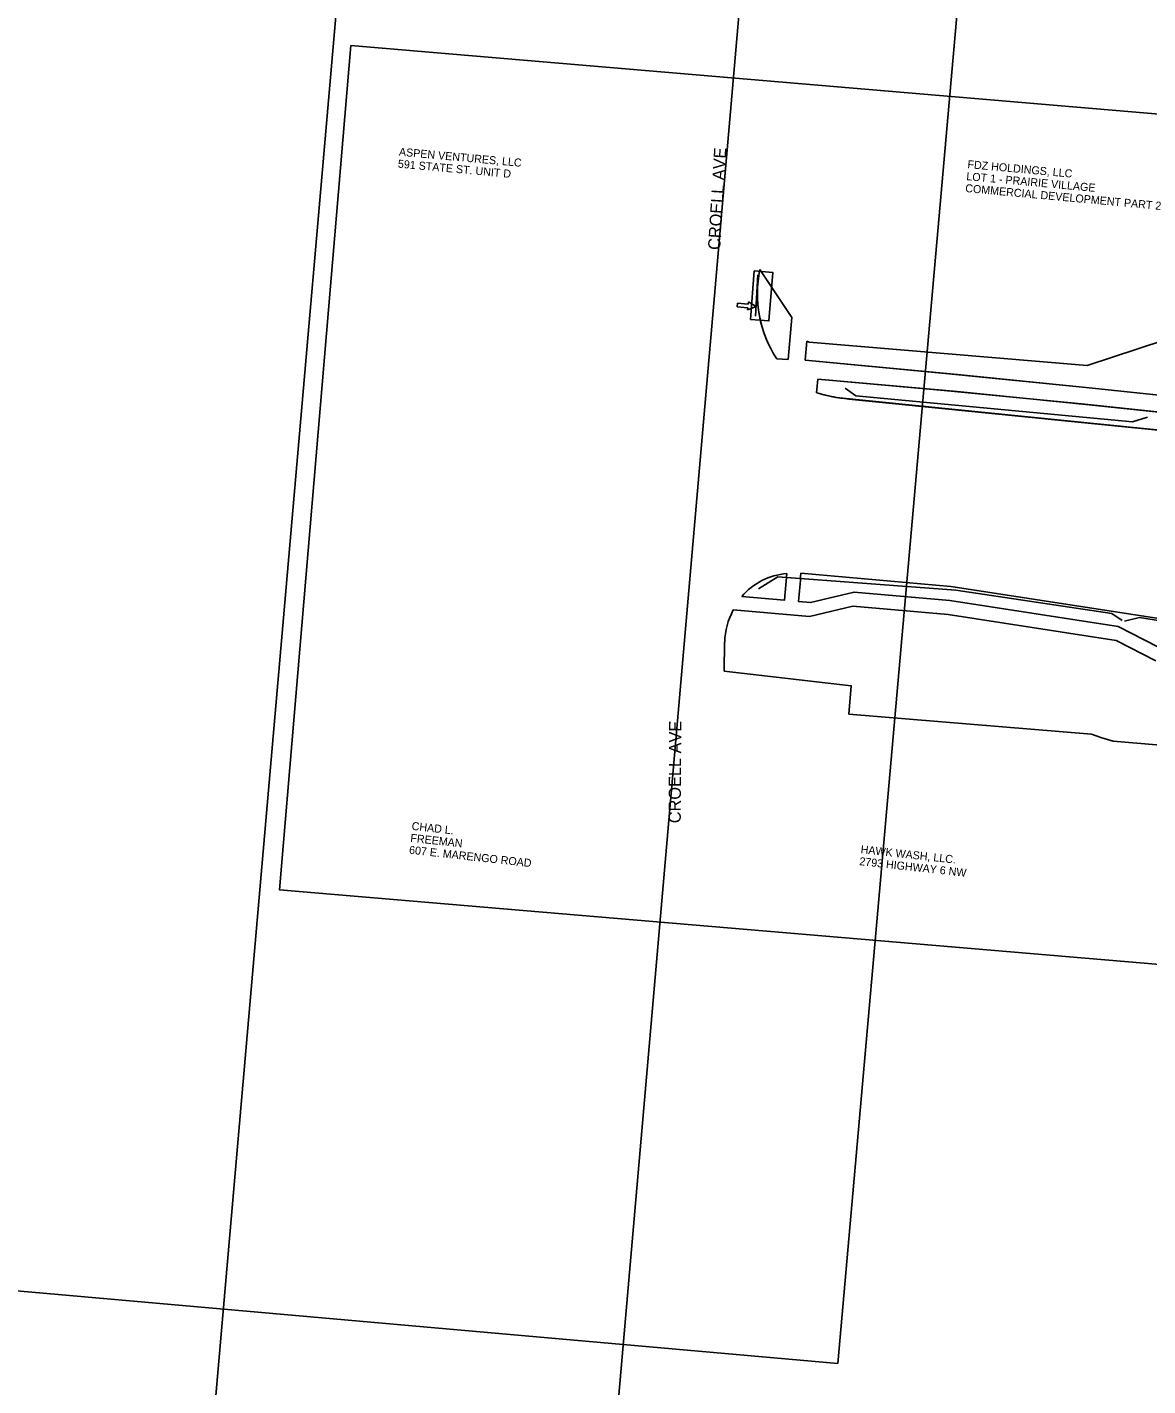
# Model space of a CAD drawing. Extents: x 20499990 to 20505779, y 7953198 to 7954399.
# Drawn here: x 20502321.1 to 20502718.2, y 7953510.9 to 7953992.1 of the extents above; entities that cross this region are included whole.
import ezdxf

# ---------------------------------------------------------------- set-up
doc = ezdxf.new("R2010")
doc.units = 0
for name, color, linetype in [('Building', 7, 'Continuous'), ('Draft_DNC', 7, 'Continuous'), ('dsnCellElements', 7, 'Continuous'), ('ErosionControl', 7, 'Continuous'), ('NamedBoundary', 7, 'Continuous'), ('Seeding', 7, 'Continuous'), ('Text', 7, 'Continuous')]:
    doc.layers.add(name, color=color, linetype=linetype)

msp = doc.modelspace()

# ---------------------------------------------------------------- linework, layer by layer
at = {"layer": 'Building'}
for p, q in [((20502592.07, 7953889.26), (20502580.67, 7953906.21)), ((20502590.76, 7953874.33), (20502592.07, 7953889.26)), ((20502597.36, 7953880.88), (20502596.77, 7953874.12)), ((20502586.67, 7953874.66), (20502590.76, 7953874.33)), ((20502648.32, 7953794.05), (20502595.26, 7953798.66)), ((20502826.66, 7953766.57), (20502648.32, 7953794.05)), ((20502568.22, 7953774.31), (20502567.99, 7953764))]:
    msp.add_line(p, q, dxfattribs=at)
for points in [[(20503191.67, 7953845.98), (20503160.23, 7953834.67), (20502997.8, 7953862.16), (20502732.96, 7953884.23), (20502696.7, 7953872.21), (20502598.22, 7953880.54), (20502597.36, 7953880.88)], [(20502596.77, 7953874.12), (20502646.43, 7953869.48), (20502697.39, 7953864.38), (20502801.98, 7953853.37), (20502961.27, 7953836.6), (20503050, 7953824.21), (20503141.39, 7953813.56), (20503181.6, 7953810.21)], [(20502600.82, 7953862.58), (20502601.24, 7953867.37), (20502650.63, 7953863.01), (20502697.4, 7953858.35), (20502809.34, 7953846.56), (20502960.51, 7953830.65), (20503008.42, 7953823.59), (20503140.79, 7953807.58), (20503176.04, 7953804.65)], [(20502959.75, 7953824.69), (20502796.27, 7953841.89), (20502607.78, 7953860.95)], [(20502574.26, 7953790.45), (20502589.41, 7953789.14), (20502590.23, 7953798.57)], [(20502594.39, 7953788.7), (20502598.67, 7953788.33), (20502614.05, 7953792.01), (20502648, 7953789.06)], [(20502720.94, 7953767.64), (20502706.88, 7953774.87), (20502647.4, 7953784.09), (20502613.61, 7953787.03), (20502598.23, 7953783.35), (20502571.26, 7953785.7)], [(20502648, 7953789.06), (20502707.64, 7953779.82), (20502721.7, 7953772.58), (20502825.48, 7953756.63)], [(20502567.99, 7953764), (20502613.1, 7953758.85), (20502612.25, 7953748.82), (20502698.25, 7953741.67), (20502701.89, 7953740.37), (20502705.93, 7953739.22), (20503089.85, 7953706.77), (20503113.09, 7953702.02), (20503112.96, 7953691.99), (20503200.66, 7953684.68), (20503201.45, 7953693.28)]]:
    msp.add_lwpolyline(points, dxfattribs=at)
for centre, radius, start, end in [((20502622.32, 7953897.78), 42.5, 168.5626, 212.9608), ((20502618.28, 7953921.35), 61.3, 253.4547, 260.1372), ((20502591.96, 7953775.4), 23.23, 94.2718, 139.6131), ((20507248.85, 7953388.67), 4671.62, 174.96513, 175.08777), ((20502593.22, 7953773.75), 25, 151.4483, 178.7029)]:
    msp.add_arc(centre, radius, start, end, dxfattribs=at)
at = {"layer": 'Draft_DNC'}
for points in [[(20502378.98, 7953404.37), (20502465.54, 7954399.08), (20505611.36, 7954341.07), (20505615.95, 7953217.82)], [(20502519.96, 7953384.14), (20502606.52, 7954378.84), (20505752.34, 7954320.84), (20505756.93, 7953197.59)]]:
    msp.add_lwpolyline(points, close=True, dxfattribs=at)
at = {"layer": 'dsnCellElements'}
for p, q in [((20502572.64, 7953893.06), (20502572.75, 7953894.33)), ((20502576.44, 7953892.72), (20502572.64, 7953893.06)), ((20502572.75, 7953894.33), (20502576.55, 7953893.99)), ((20502579.34, 7953893.1), (20502576.37, 7953891.93)), ((20502576.37, 7953891.93), (20502576.44, 7953892.72)), ((20502576.55, 7953893.99), (20502576.62, 7953894.78)), ((20502576.62, 7953894.78), (20502579.34, 7953893.1))]:
    msp.add_line(p, q, dxfattribs=at)
at = {"layer": 'ErosionControl'}
msp.add_line((20502579.15, 7953889.78), (20502579.94, 7953904.39), dxfattribs=at)
msp.add_lwpolyline([(20502577.35, 7953888.58), (20502583.89, 7953888.07), (20502585.24, 7953905.24), (20502578.71, 7953905.76)], close=True, dxfattribs=at)
for points in [[(20502610.86, 7953864.28), (20502614.74, 7953861.49), (20502712.67, 7953852.26), (20502718.09, 7953853.95)], [(20502590.23, 7953798.57), (20502589.41, 7953789.14), (20502574.26, 7953790.45)], [(20502709.02, 7953781.96), (20502705.44, 7953784.47), (20502650.07, 7953792.71), (20502587.01, 7953797.37), (20502580.25, 7953793.19)], [(20502842.12, 7953761.3), (20502839.46, 7953764.5), (20502826.3, 7953765.33), (20502715.26, 7953783.03), (20502709.93, 7953781.73)]]:
    msp.add_lwpolyline(points, dxfattribs=at)
msp.add_arc((20502591.96, 7953775.4), 23.23, 94.2718, 139.6131, dxfattribs=at)
at = {"layer": 'NamedBoundary'}
for points in [[(20501724.26, 7954199.37), (20501671.43, 7953601.7), (20502608.28, 7953518.89), (20502661.11, 7954116.56)], [(20502435.82, 7953985.54), (20502410.46, 7953686.62), (20503347.59, 7953607.1), (20503372.96, 7953906.03)]]:
    msp.add_lwpolyline(points, close=True, dxfattribs=at)
at = {"layer": 'Seeding'}
for p, q in [((20502592.07, 7953889.26), (20502580.67, 7953906.24)), ((20502590.76, 7953874.33), (20502592.07, 7953889.26)), ((20502597.36, 7953880.88), (20502596.77, 7953874.12)), ((20502586.67, 7953874.66), (20502590.76, 7953874.33)), ((20502648.32, 7953794.05), (20502595.26, 7953798.66)), ((20502826.66, 7953766.57), (20502648.32, 7953794.05)), ((20502568.22, 7953774.31), (20502567.99, 7953764))]:
    msp.add_line(p, q, dxfattribs=at)
for points in [[(20503191.67, 7953845.98), (20503160.23, 7953834.67), (20502997.8, 7953862.16), (20502732.96, 7953884.23), (20502696.7, 7953872.21), (20502598.22, 7953880.54), (20502597.36, 7953880.88)], [(20502596.77, 7953874.12), (20502650.75, 7953869.08), (20502697.39, 7953864.38), (20502818.79, 7953851.6), (20502961.27, 7953836.6), (20503026.56, 7953826.95), (20503141.39, 7953813.56), (20503181.6, 7953810.21)], [(20502600.82, 7953862.58), (20502601.24, 7953867.37), (20502646.05, 7953863.46), (20502695.83, 7953858.51), (20502809.34, 7953846.56), (20502960.51, 7953830.65), (20503009.88, 7953823.38), (20503140.79, 7953807.58), (20503176.04, 7953804.65)], [(20502959.75, 7953824.69), (20502798.39, 7953841.68), (20502612.16, 7953860.35)], [(20502590.23, 7953798.57), (20502589.41, 7953789.14), (20502574.26, 7953790.45)], [(20502594.39, 7953788.7), (20502598.67, 7953788.33), (20502614.05, 7953792.01), (20502648, 7953789.06)], [(20502720.94, 7953767.64), (20502706.88, 7953774.87), (20502647.4, 7953784.09), (20502613.61, 7953787.03), (20502598.23, 7953783.35), (20502571.26, 7953785.7)], [(20502648, 7953789.06), (20502707.64, 7953779.82), (20502721.7, 7953772.58), (20502825.48, 7953756.63)], [(20502567.99, 7953764), (20502613.1, 7953758.85), (20502612.25, 7953748.82), (20502698.25, 7953741.67), (20502701.89, 7953740.37), (20502705.93, 7953739.22), (20503089.85, 7953706.77), (20503113.09, 7953702.02), (20503112.96, 7953691.99), (20503200.66, 7953684.68), (20503201.45, 7953693.28)]]:
    msp.add_lwpolyline(points, dxfattribs=at)
for centre, radius, start, end in [((20502621.8, 7953897.69), 42, 168.248, 213.2435), ((20502618.28, 7953921.35), 61.3, 253.4547, 264.2749), ((20502591.96, 7953775.4), 23.23, 94.2718, 139.6131), ((20499771.05, 7954039.42), 2834.45, 354.92538, 355.12752), ((20502593.22, 7953773.75), 25, 151.4483, 178.7029)]:
    msp.add_arc(centre, radius, start, end, dxfattribs=at)

# ---------------------------------------------------------------- texts
at = {"layer": 'Text'}
for s, height, rotation, p in [('591 STATE ST. UNIT D', 2.8346, 354.7645, (20502452.35, 7953942.36)), ('ASPEN VENTURES, LLC', 2.8346, 354.7645, (20502452.73, 7953946.59)), ('CROELL AVE', 4.32, 86.4392, (20502566.59, 7953913.08)), ('LOT 1 - PRAIRIE VILLAGE', 2.8346, 354.7645, (20502653.76, 7953937.93)), ('FDZ HOLDINGS, LLC', 2.8346, 354.7645, (20502654.15, 7953942.17)), ('COMMERCIAL DEVELOPMENT PART 2', 2.8346, 354.7645, (20502653.37, 7953933.7)), ('CROELL AVE', 4.32, 89.6519, (20502552.66, 7953710.15)), ('CHAD L.', 2.835, 353.7082, (20502457.22, 7953707.85)), ('FREEMAN', 2.835, 353.7082, (20502456.75, 7953703.62)), ('607 E. MARENGO ROAD', 2.8346, 353.7082, (20502456.29, 7953699.4)), ('HAWK WASH, LLC.', 2.8346, 353.7082, (20502616.29, 7953699.58)), ('2793 HIGHWAY 6 NW', 2.8346, 353.7082, (20502615.83, 7953695.36))]:
    msp.add_text(s, height=height, rotation=rotation, dxfattribs=at).set_placement(p)

doc.saveas('drawing.dxf')
